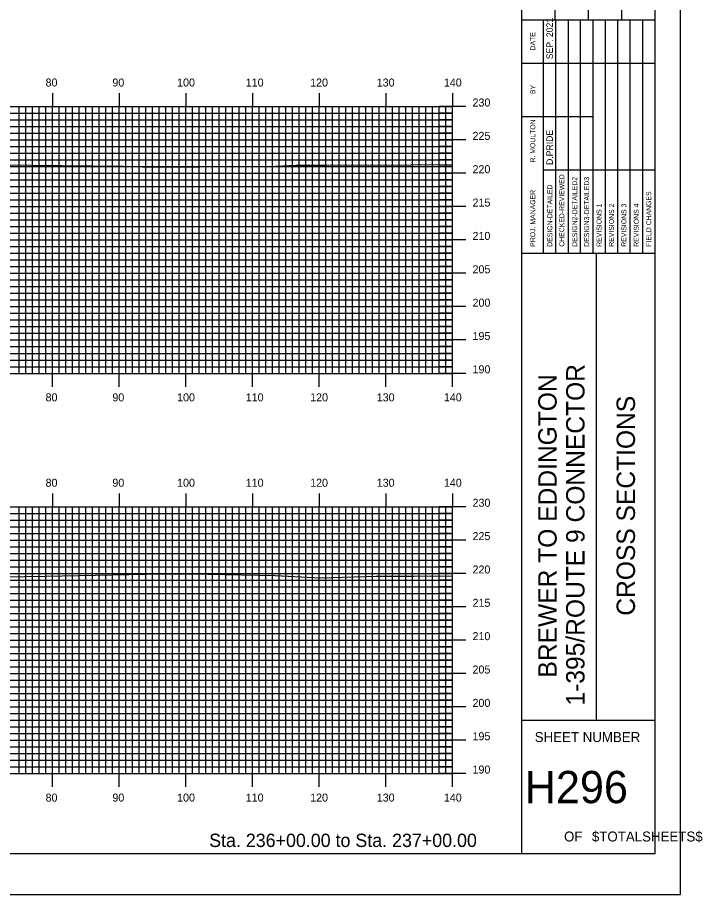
# Model space of a CAD drawing. Extents: x 1800749 to 1801092, y 442591 to 442811.
# Drawn here: x 1800989.3 to 1801092, y 442590.5 to 442722 of the extents above; entities that cross this region are included whole.
import ezdxf

# ---------------------------------------------------------------- set-up
doc = ezdxf.new("R2010")
doc.units = 0
for name, color, linetype in [('ANNOTATION', 7, 'Continuous'), ('BORDER', 7, 'Continuous'), ('H_V ANNOTATION', 7, 'Continuous'), ('MAJOR', 7, 'Continuous'), ('MINOR', 7, 'Continuous'), ('PLOT BOUNDARY', 7, 'Continuous'), ('S_Roadway_Centerline', 7, 'Continuous')]:
    doc.layers.add(name, color=color, linetype=linetype)

msp = doc.modelspace()

# ---------------------------------------------------------------- linework, layer by layer
at = {"layer": 'ANNOTATION'}
msp.add_line((1801054.55, 442688.67), (1801054.55, 442691.67), dxfattribs=at)
at = {"layer": 'BORDER'}
for p, q in [((1801064.95, 442596.67), (1801064.95, 442806.67)), ((1801069.95, 442721.67), (1801069.95, 442738.97)), ((1801074.95, 442721.67), (1801074.95, 442738.97)), ((1801079.95, 442721.67), (1801079.95, 442738.97)), ((1801064.95, 442721.67), (1801084.95, 442721.67)), ((1801064.95, 442686.67), (1801084.95, 442686.67)), ((1801076.13, 442616.67), (1801076.13, 442686.67)), ((1801064.95, 442616.67), (1801084.95, 442616.67))]:
    msp.add_line(p, q, dxfattribs=at)
msp.add_lwpolyline([(1800764.95, 442596.67), (1801084.95, 442596.67), (1801084.95, 442806.67), (1800764.95, 442806.67)], close=True, dxfattribs=at)
for points in [[(1801068.18, 442715.17), (1801068.18, 442721.67)], [(1801070.04, 442686.68), (1801070.04, 442721.67)], [(1801071.91, 442721.67), (1801071.91, 442686.68)], [(1801073.77, 442686.68), (1801073.77, 442721.67)], [(1801075.63, 442686.68), (1801075.63, 442721.67)], [(1801077.5, 442686.68), (1801077.5, 442721.67)], [(1801079.36, 442686.68), (1801079.36, 442721.67)], [(1801081.22, 442686.68), (1801081.22, 442721.67)], [(1801083.09, 442686.68), (1801083.09, 442721.67)], [(1801068.18, 442686.68), (1801068.18, 442720.26)], [(1801064.95, 442715.17), (1801084.95, 442715.17)], [(1801064.95, 442707.17), (1801068.18, 442707.17)], [(1801068.18, 442707.17), (1801075.63, 442707.17)], [(1801068.18, 442699.17), (1801084.95, 442699.17)]]:
    msp.add_lwpolyline(points, dxfattribs=at)
at = {"layer": 'MAJOR'}
for p, q in [((1800994.55, 442710.67), (1800994.55, 442708.67)), ((1801004.55, 442710.67), (1801004.55, 442708.67)), ((1801014.55, 442710.67), (1801014.55, 442708.67)), ((1801024.55, 442710.67), (1801024.55, 442708.67)), ((1801034.55, 442710.67), (1801034.55, 442708.67)), ((1801044.55, 442710.67), (1801044.55, 442708.67)), ((1801054.55, 442710.67), (1801054.55, 442708.67)), ((1800774.55, 442708.67), (1801054.55, 442708.67)), ((1800774.55, 442708.67), (1801054.55, 442708.67)), ((1800994.55, 442668.67), (1800994.55, 442708.67)), ((1801004.55, 442668.67), (1801004.55, 442708.67)), ((1801014.55, 442668.67), (1801014.55, 442708.67)), ((1801024.55, 442668.67), (1801024.55, 442708.67)), ((1801034.55, 442668.67), (1801034.55, 442708.67)), ((1801044.55, 442668.67), (1801044.55, 442708.67)), ((1801056.55, 442708.67), (1801052.55, 442708.67)), ((1801054.55, 442668.67), (1801054.55, 442708.67)), ((1801054.55, 442668.67), (1801054.55, 442708.67)), ((1800774.55, 442703.67), (1801054.55, 442703.67)), ((1801056.55, 442703.67), (1801052.55, 442703.67)), ((1800774.55, 442698.67), (1801054.55, 442698.67)), ((1801056.55, 442698.67), (1801052.55, 442698.67)), ((1800774.55, 442693.67), (1801054.55, 442693.67)), ((1801056.55, 442693.67), (1801052.55, 442693.67)), ((1800774.55, 442688.67), (1801054.55, 442688.67)), ((1801056.55, 442688.67), (1801052.55, 442688.67)), ((1800774.55, 442683.67), (1801054.55, 442683.67)), ((1801056.55, 442683.67), (1801052.55, 442683.67)), ((1800774.55, 442678.67), (1801054.55, 442678.67)), ((1801056.55, 442678.67), (1801052.55, 442678.67)), ((1800774.55, 442673.67), (1801054.55, 442673.67)), ((1801056.55, 442673.67), (1801052.55, 442673.67)), ((1800774.55, 442668.67), (1801054.55, 442668.67)), ((1800774.55, 442668.67), (1801054.55, 442668.67)), ((1800994.55, 442666.66), (1800994.55, 442668.67)), ((1801004.55, 442666.66), (1801004.55, 442668.67)), ((1801014.55, 442666.66), (1801014.55, 442668.67)), ((1801024.55, 442666.66), (1801024.55, 442668.67)), ((1801034.55, 442666.66), (1801034.55, 442668.67)), ((1801044.55, 442666.66), (1801044.55, 442668.67)), ((1801056.55, 442668.67), (1801052.55, 442668.67)), ((1801054.55, 442666.66), (1801054.55, 442668.67)), ((1800994.55, 442650.67), (1800994.55, 442648.67)), ((1801004.55, 442650.67), (1801004.55, 442648.67)), ((1801014.55, 442650.67), (1801014.55, 442648.67)), ((1801024.55, 442650.67), (1801024.55, 442648.67)), ((1801034.55, 442650.67), (1801034.55, 442648.67)), ((1801044.55, 442650.67), (1801044.55, 442648.67)), ((1801054.55, 442650.67), (1801054.55, 442648.67)), ((1800774.55, 442648.67), (1801054.55, 442648.67)), ((1800774.55, 442648.67), (1801054.55, 442648.67)), ((1800994.55, 442608.67), (1800994.55, 442648.67)), ((1801004.55, 442608.67), (1801004.55, 442648.67)), ((1801014.55, 442608.67), (1801014.55, 442648.67)), ((1801024.55, 442608.67), (1801024.55, 442648.67)), ((1801034.55, 442608.67), (1801034.55, 442648.67)), ((1801044.55, 442608.67), (1801044.55, 442648.67)), ((1801056.55, 442648.67), (1801052.55, 442648.67)), ((1801054.55, 442608.67), (1801054.55, 442648.67)), ((1801054.55, 442608.67), (1801054.55, 442648.67)), ((1800774.55, 442643.67), (1801054.55, 442643.67)), ((1801056.55, 442643.67), (1801052.55, 442643.67)), ((1800774.55, 442638.67), (1801054.55, 442638.67)), ((1801056.55, 442638.67), (1801052.55, 442638.67)), ((1800774.55, 442633.67), (1801054.55, 442633.67)), ((1801056.55, 442633.67), (1801052.55, 442633.67)), ((1800774.55, 442628.67), (1801054.55, 442628.67)), ((1801056.55, 442628.67), (1801052.55, 442628.67)), ((1800774.55, 442623.67), (1801054.55, 442623.67)), ((1801056.55, 442623.67), (1801052.55, 442623.67)), ((1800774.55, 442618.67), (1801054.55, 442618.67)), ((1801056.55, 442618.67), (1801052.55, 442618.67)), ((1800774.55, 442613.67), (1801054.55, 442613.67)), ((1801056.55, 442613.67), (1801052.55, 442613.67)), ((1800774.55, 442608.67), (1801054.55, 442608.67)), ((1800774.55, 442608.67), (1801054.55, 442608.67)), ((1800994.55, 442606.66), (1800994.55, 442608.67)), ((1801004.55, 442606.66), (1801004.55, 442608.67)), ((1801014.55, 442606.66), (1801014.55, 442608.67)), ((1801024.55, 442606.66), (1801024.55, 442608.67)), ((1801034.55, 442606.66), (1801034.55, 442608.67)), ((1801044.55, 442606.66), (1801044.55, 442608.67)), ((1801056.55, 442608.67), (1801052.55, 442608.67)), ((1801054.55, 442606.66), (1801054.55, 442608.67))]:
    msp.add_line(p, q, dxfattribs=at)
at = {"layer": 'MINOR'}
for p, q in [((1800989.55, 442668.67), (1800989.55, 442708.67)), ((1800990.55, 442668.67), (1800990.55, 442708.67)), ((1800991.55, 442668.67), (1800991.55, 442708.67)), ((1800992.55, 442668.67), (1800992.55, 442708.67)), ((1800993.55, 442668.67), (1800993.55, 442708.67)), ((1800995.55, 442668.67), (1800995.55, 442708.67)), ((1800996.55, 442668.67), (1800996.55, 442708.67)), ((1800997.55, 442668.67), (1800997.55, 442708.67)), ((1800998.55, 442668.67), (1800998.55, 442708.67)), ((1800999.55, 442668.67), (1800999.55, 442708.67)), ((1801000.55, 442668.67), (1801000.55, 442708.67)), ((1801001.55, 442668.67), (1801001.55, 442708.67)), ((1801002.55, 442668.67), (1801002.55, 442708.67)), ((1801003.55, 442668.67), (1801003.55, 442708.67)), ((1801005.55, 442668.67), (1801005.55, 442708.67)), ((1801006.55, 442668.67), (1801006.55, 442708.67)), ((1801007.55, 442668.67), (1801007.55, 442708.67)), ((1801008.55, 442668.67), (1801008.55, 442708.67)), ((1801009.55, 442668.67), (1801009.55, 442708.67)), ((1801010.55, 442668.67), (1801010.55, 442708.67)), ((1801011.55, 442668.67), (1801011.55, 442708.67)), ((1801012.55, 442668.67), (1801012.55, 442708.67)), ((1801013.55, 442668.67), (1801013.55, 442708.67)), ((1801015.55, 442668.67), (1801015.55, 442708.67)), ((1801016.55, 442668.67), (1801016.55, 442708.67)), ((1801017.55, 442668.67), (1801017.55, 442708.67)), ((1801018.55, 442668.67), (1801018.55, 442708.67)), ((1801019.55, 442668.67), (1801019.55, 442708.67)), ((1801020.55, 442668.67), (1801020.55, 442708.67)), ((1801021.55, 442668.67), (1801021.55, 442708.67)), ((1801022.55, 442668.67), (1801022.55, 442708.67)), ((1801023.55, 442668.67), (1801023.55, 442708.67)), ((1801025.55, 442668.67), (1801025.55, 442708.67)), ((1801026.55, 442668.67), (1801026.55, 442708.67)), ((1801027.55, 442668.67), (1801027.55, 442708.67)), ((1801028.55, 442668.67), (1801028.55, 442708.67)), ((1801029.55, 442668.67), (1801029.55, 442708.67)), ((1801030.55, 442668.67), (1801030.55, 442708.67)), ((1801031.55, 442668.67), (1801031.55, 442708.67)), ((1801032.55, 442668.67), (1801032.55, 442708.67)), ((1801033.55, 442668.67), (1801033.55, 442708.67)), ((1801035.55, 442668.67), (1801035.55, 442708.67)), ((1801036.55, 442668.67), (1801036.55, 442708.67)), ((1801037.55, 442668.67), (1801037.55, 442708.67)), ((1801038.55, 442668.67), (1801038.55, 442708.67)), ((1801039.55, 442668.67), (1801039.55, 442708.67)), ((1801040.55, 442668.67), (1801040.55, 442708.67)), ((1801041.55, 442668.67), (1801041.55, 442708.67)), ((1801042.55, 442668.67), (1801042.55, 442708.67)), ((1801043.55, 442668.67), (1801043.55, 442708.67)), ((1801045.55, 442668.67), (1801045.55, 442708.67)), ((1801046.55, 442668.67), (1801046.55, 442708.67)), ((1801047.55, 442668.67), (1801047.55, 442708.67)), ((1801048.55, 442668.67), (1801048.55, 442708.67)), ((1801049.55, 442668.67), (1801049.55, 442708.67)), ((1801050.55, 442668.67), (1801050.55, 442708.67)), ((1801051.55, 442668.67), (1801051.55, 442708.67)), ((1801052.55, 442668.67), (1801052.55, 442708.67)), ((1801053.55, 442668.67), (1801053.55, 442708.67)), ((1800774.55, 442707.67), (1801054.55, 442707.67)), ((1801054.55, 442707.67), (1801052.55, 442707.67)), ((1800774.55, 442706.67), (1801054.55, 442706.67)), ((1800774.55, 442705.67), (1801054.55, 442705.67)), ((1801054.55, 442706.67), (1801052.55, 442706.67)), ((1801054.55, 442705.67), (1801052.55, 442705.67)), ((1800774.55, 442704.67), (1801054.55, 442704.67)), ((1801054.55, 442704.67), (1801052.55, 442704.67)), ((1800774.55, 442702.67), (1801054.55, 442702.67)), ((1800774.55, 442701.67), (1801054.55, 442701.67)), ((1801054.55, 442702.67), (1801052.55, 442702.67)), ((1801054.55, 442701.67), (1801052.55, 442701.67)), ((1800774.55, 442700.67), (1801054.55, 442700.67)), ((1801054.55, 442700.67), (1801052.55, 442700.67)), ((1800774.55, 442699.67), (1801054.55, 442699.67)), ((1801054.55, 442699.67), (1801052.55, 442699.67)), ((1800774.55, 442697.67), (1801054.55, 442697.67)), ((1801054.55, 442697.67), (1801052.55, 442697.67)), ((1800774.55, 442696.67), (1801054.55, 442696.67)), ((1801054.55, 442696.67), (1801052.55, 442696.67)), ((1800774.55, 442695.67), (1801054.55, 442695.67)), ((1801054.55, 442695.67), (1801052.55, 442695.67)), ((1800774.55, 442694.67), (1801054.55, 442694.67)), ((1801054.55, 442694.67), (1801052.55, 442694.67)), ((1800774.55, 442692.67), (1801054.55, 442692.67)), ((1801054.55, 442692.67), (1801052.55, 442692.67)), ((1800774.55, 442691.67), (1801054.55, 442691.67)), ((1801054.55, 442691.67), (1801052.55, 442691.67)), ((1800774.55, 442690.67), (1801054.55, 442690.67)), ((1801054.55, 442690.67), (1801052.55, 442690.67)), ((1800774.55, 442689.67), (1801054.55, 442689.67)), ((1801054.55, 442689.67), (1801052.55, 442689.67)), ((1800774.55, 442687.67), (1801054.55, 442687.67)), ((1801054.55, 442687.67), (1801052.55, 442687.67)), ((1800774.55, 442686.67), (1801054.55, 442686.67)), ((1801054.55, 442686.67), (1801052.55, 442686.67)), ((1800774.55, 442685.67), (1801054.55, 442685.67)), ((1800774.55, 442684.67), (1801054.55, 442684.67)), ((1801054.55, 442685.67), (1801052.55, 442685.67)), ((1801054.55, 442684.67), (1801052.55, 442684.67)), ((1800774.55, 442682.67), (1801054.55, 442682.67)), ((1801054.55, 442682.67), (1801052.55, 442682.67)), ((1800774.55, 442681.67), (1801054.55, 442681.67)), ((1800774.55, 442680.67), (1801054.55, 442680.67)), ((1801054.55, 442681.67), (1801052.55, 442681.67)), ((1801054.55, 442680.67), (1801052.55, 442680.67)), ((1800774.55, 442679.67), (1801054.55, 442679.67)), ((1801054.55, 442679.67), (1801052.55, 442679.67)), ((1800774.55, 442677.67), (1801054.55, 442677.67)), ((1800774.55, 442676.67), (1801054.55, 442676.67)), ((1801054.55, 442677.67), (1801052.55, 442677.67)), ((1801054.55, 442676.67), (1801052.55, 442676.67)), ((1800774.55, 442675.67), (1801054.55, 442675.67)), ((1801054.55, 442675.67), (1801052.55, 442675.67)), ((1800774.55, 442674.67), (1801054.55, 442674.67)), ((1801054.55, 442674.67), (1801052.55, 442674.67)), ((1800774.55, 442672.67), (1801054.55, 442672.67)), ((1801054.55, 442672.67), (1801052.55, 442672.67)), ((1800774.55, 442671.67), (1801054.55, 442671.67)), ((1801054.55, 442671.67), (1801052.55, 442671.67)), ((1800774.55, 442670.67), (1801054.55, 442670.67)), ((1801054.55, 442670.67), (1801052.55, 442670.67)), ((1800774.55, 442669.67), (1801054.55, 442669.67)), ((1801054.55, 442669.67), (1801052.55, 442669.67)), ((1800774.55, 442647.67), (1801054.55, 442647.67)), ((1800989.55, 442608.67), (1800989.55, 442648.67)), ((1800990.55, 442608.67), (1800990.55, 442648.67)), ((1800991.55, 442608.67), (1800991.55, 442648.67)), ((1800992.55, 442608.67), (1800992.55, 442648.67)), ((1800993.55, 442608.67), (1800993.55, 442648.67)), ((1800995.55, 442608.67), (1800995.55, 442648.67)), ((1800996.55, 442608.67), (1800996.55, 442648.67)), ((1800997.55, 442608.67), (1800997.55, 442648.67)), ((1800998.55, 442608.67), (1800998.55, 442648.67)), ((1800999.55, 442608.67), (1800999.55, 442648.67)), ((1801000.55, 442608.67), (1801000.55, 442648.67)), ((1801001.55, 442608.67), (1801001.55, 442648.67)), ((1801002.55, 442608.67), (1801002.55, 442648.67)), ((1801003.55, 442608.67), (1801003.55, 442648.67)), ((1801005.55, 442608.67), (1801005.55, 442648.67)), ((1801006.55, 442608.67), (1801006.55, 442648.67)), ((1801007.55, 442608.67), (1801007.55, 442648.67)), ((1801008.55, 442608.67), (1801008.55, 442648.67)), ((1801009.55, 442608.67), (1801009.55, 442648.67)), ((1801010.55, 442608.67), (1801010.55, 442648.67)), ((1801011.55, 442608.67), (1801011.55, 442648.67)), ((1801012.55, 442608.67), (1801012.55, 442648.67)), ((1801013.55, 442608.67), (1801013.55, 442648.67)), ((1801015.55, 442608.67), (1801015.55, 442648.67)), ((1801016.55, 442608.67), (1801016.55, 442648.67)), ((1801017.55, 442608.67), (1801017.55, 442648.67)), ((1801018.55, 442608.67), (1801018.55, 442648.67)), ((1801019.55, 442608.67), (1801019.55, 442648.67)), ((1801020.55, 442608.67), (1801020.55, 442648.67)), ((1801021.55, 442608.67), (1801021.55, 442648.67)), ((1801022.55, 442608.67), (1801022.55, 442648.67)), ((1801023.55, 442608.67), (1801023.55, 442648.67)), ((1801025.55, 442608.67), (1801025.55, 442648.67)), ((1801026.55, 442608.67), (1801026.55, 442648.67)), ((1801027.55, 442608.67), (1801027.55, 442648.67)), ((1801028.55, 442608.67), (1801028.55, 442648.67)), ((1801029.55, 442608.67), (1801029.55, 442648.67)), ((1801030.55, 442608.67), (1801030.55, 442648.67)), ((1801031.55, 442608.67), (1801031.55, 442648.67)), ((1801032.55, 442608.67), (1801032.55, 442648.67)), ((1801033.55, 442608.67), (1801033.55, 442648.67)), ((1801035.55, 442608.67), (1801035.55, 442648.67)), ((1801036.55, 442608.67), (1801036.55, 442648.67)), ((1801037.55, 442608.67), (1801037.55, 442648.67)), ((1801038.55, 442608.67), (1801038.55, 442648.67)), ((1801039.55, 442608.67), (1801039.55, 442648.67)), ((1801040.55, 442608.67), (1801040.55, 442648.67)), ((1801041.55, 442608.67), (1801041.55, 442648.67)), ((1801042.55, 442608.67), (1801042.55, 442648.67)), ((1801043.55, 442608.67), (1801043.55, 442648.67)), ((1801045.55, 442608.67), (1801045.55, 442648.67)), ((1801046.55, 442608.67), (1801046.55, 442648.67)), ((1801047.55, 442608.67), (1801047.55, 442648.67)), ((1801048.55, 442608.67), (1801048.55, 442648.67)), ((1801049.55, 442608.67), (1801049.55, 442648.67)), ((1801050.55, 442608.67), (1801050.55, 442648.67)), ((1801051.55, 442608.67), (1801051.55, 442648.67)), ((1801052.55, 442608.67), (1801052.55, 442648.67)), ((1801054.55, 442647.67), (1801052.55, 442647.67)), ((1801053.55, 442608.67), (1801053.55, 442648.67)), ((1800774.55, 442646.67), (1801054.55, 442646.67)), ((1801054.55, 442646.67), (1801052.55, 442646.67)), ((1800774.55, 442645.67), (1801054.55, 442645.67)), ((1801054.55, 442645.67), (1801052.55, 442645.67)), ((1800774.55, 442644.67), (1801054.55, 442644.67)), ((1801054.55, 442644.67), (1801052.55, 442644.67)), ((1800774.55, 442642.67), (1801054.55, 442642.67)), ((1801054.55, 442642.67), (1801052.55, 442642.67)), ((1800774.55, 442641.67), (1801054.55, 442641.67)), ((1801054.55, 442641.67), (1801052.55, 442641.67)), ((1800774.55, 442640.67), (1801054.55, 442640.67)), ((1801054.55, 442640.67), (1801052.55, 442640.67)), ((1800774.55, 442639.67), (1801054.55, 442639.67)), ((1801054.55, 442639.67), (1801052.55, 442639.67)), ((1800774.55, 442637.67), (1801054.55, 442637.67)), ((1801054.55, 442637.67), (1801052.55, 442637.67)), ((1800774.55, 442636.67), (1801054.55, 442636.67)), ((1801054.55, 442636.67), (1801052.55, 442636.67)), ((1800774.55, 442635.67), (1801054.55, 442635.67)), ((1800774.55, 442634.67), (1801054.55, 442634.67)), ((1801054.55, 442635.67), (1801052.55, 442635.67)), ((1801054.55, 442634.67), (1801052.55, 442634.67)), ((1800774.55, 442632.67), (1801054.55, 442632.67)), ((1801054.55, 442632.67), (1801052.55, 442632.67)), ((1800774.55, 442631.67), (1801054.55, 442631.67)), ((1800774.55, 442630.67), (1801054.55, 442630.67)), ((1801054.55, 442631.67), (1801052.55, 442631.67)), ((1801054.55, 442630.67), (1801052.55, 442630.67)), ((1800774.55, 442629.67), (1801054.55, 442629.67)), ((1801054.55, 442629.67), (1801052.55, 442629.67)), ((1800774.55, 442627.67), (1801054.55, 442627.67)), ((1800774.55, 442626.67), (1801054.55, 442626.67)), ((1801054.55, 442627.67), (1801052.55, 442627.67)), ((1801054.55, 442626.67), (1801052.55, 442626.67)), ((1800774.55, 442625.67), (1801054.55, 442625.67)), ((1801054.55, 442625.67), (1801052.55, 442625.67)), ((1800774.55, 442624.67), (1801054.55, 442624.67)), ((1801054.55, 442624.67), (1801052.55, 442624.67)), ((1800774.55, 442622.67), (1801054.55, 442622.67)), ((1801054.55, 442622.67), (1801052.55, 442622.67)), ((1800774.55, 442621.67), (1801054.55, 442621.67)), ((1801054.55, 442621.67), (1801052.55, 442621.67)), ((1800774.55, 442620.67), (1801054.55, 442620.67)), ((1801054.55, 442620.67), (1801052.55, 442620.67)), ((1800774.55, 442619.67), (1801054.55, 442619.67)), ((1801054.55, 442619.67), (1801052.55, 442619.67)), ((1800774.55, 442617.67), (1801054.55, 442617.67)), ((1801054.55, 442617.67), (1801052.55, 442617.67)), ((1800774.55, 442616.67), (1801054.55, 442616.67)), ((1801054.55, 442616.67), (1801052.55, 442616.67)), ((1800774.55, 442615.67), (1801054.55, 442615.67)), ((1801054.55, 442615.67), (1801052.55, 442615.67)), ((1800774.55, 442614.67), (1801054.55, 442614.67)), ((1801054.55, 442614.67), (1801052.55, 442614.67)), ((1800774.55, 442612.67), (1801054.55, 442612.67)), ((1801054.55, 442612.67), (1801052.55, 442612.67)), ((1800774.55, 442611.67), (1801054.55, 442611.67)), ((1801054.55, 442611.67), (1801052.55, 442611.67)), ((1800774.55, 442610.67), (1801054.55, 442610.67)), ((1800774.55, 442609.67), (1801054.55, 442609.67)), ((1801054.55, 442610.67), (1801052.55, 442610.67)), ((1801054.55, 442609.67), (1801052.55, 442609.67))]:
    msp.add_line(p, q, dxfattribs=at)
at = {"layer": 'PLOT BOUNDARY'}
msp.add_lwpolyline([(1800748.76, 442590.55), (1801088.76, 442590.55), (1801088.76, 442810.55), (1800748.76, 442810.55)], close=True, dxfattribs=at)
at = {"layer": 'S_Roadway_Centerline'}
for points in [[(1800986.67, 442699.95), (1801005.14, 442699.75), (1801008.05, 442699.64), (1801011.01, 442699.58), (1801028.01, 442699.75), (1801031.11, 442699.86), (1801035.41, 442699.87), (1801048.29, 442699.94), (1801049.86, 442699.99), (1801054.55, 442699.92)], [(1800984.04, 442638.09), (1800993.51, 442638.26), (1801006, 442638.49), (1801011.31, 442638.6), (1801017.86, 442638.55), (1801027.93, 442638.34), (1801034.73, 442638.03), (1801043.09, 442638.26), (1801048.75, 442638.26), (1801054.55, 442638.32)]]:
    msp.add_lwpolyline(points, dxfattribs=at)

# ---------------------------------------------------------------- texts
at = {"layer": 'BORDER'}
for s, height, p in [('SEP. 2021', 0.969, (1801069.6, 442715.76)), ('DATE', 0.743, (1801066.96, 442717.08)), ('BY', 0.743, (1801066.96, 442710.54)), ('R. MOULTON', 0.745, (1801066.96, 442700.28)), ('D.PRIDE', 0.969, (1801069.6, 442699.92)), ('CHECKED-REVIEWED', 0.7455, (1801071.31, 442687.65)), ('DESIGN2-DETAILED2', 0.7455, (1801073.25, 442687.65)), ('DESIGN3-DETAILED3', 0.7455, (1801075.04, 442687.65)), ('DESIGN-DETAILED', 0.7455, (1801069.52, 442687.65)), ('PROJ. MANAGER', 0.7455, (1801066.96, 442687.65)), ('FIELD CHANGES', 0.7455, (1801084.35, 442687.65)), ('REVISIONS 1', 0.7455, (1801076.9, 442687.65)), ('REVISIONS 2', 0.7455, (1801078.76, 442687.65)), ('REVISIONS 3', 0.7455, (1801080.63, 442687.65)), ('REVISIONS 4', 0.7455, (1801082.49, 442687.65)), ('1-395/ROUTE 9 CONNECTOR', 2.7557, (1801074.35, 442618.87)), ('BREWER TO EDDINGTON', 2.7557, (1801070.17, 442623.07)), ('CROSS SECTIONS', 2.7557, (1801081.92, 442632.34))]:
    msp.add_text(s, height=height, rotation=90, dxfattribs=at).set_placement(p)
for s, height, p in [('SHEET NUMBER', 1.4905, (1801066.88, 442613.4)), ('H296', 4.839, (1801065.39, 442604.23)), ('OF', 1.491, (1801071.28, 442598.49)), ('$TOTALSHEETS$', 1.4905, (1801075.46, 442598.49))]:
    msp.add_text(s, height=height, dxfattribs=at).set_placement(p)
at = {"layer": 'H_V ANNOTATION'}
for s, height, p in [('80', 1.2, (1800993.5, 442711.67)), ('90', 1.2, (1801003.52, 442711.67)), ('100', 1.2, (1801013.23, 442711.67)), ('110', 1.2, (1801023.53, 442711.67)), ('120', 1.2, (1801033.19, 442711.67)), ('130', 1.2, (1801043.18, 442711.67)), ('140', 1.2, (1801053.25, 442711.67)), ('230', 1.2, (1801057.55, 442708.67)), ('225', 1.2, (1801057.55, 442703.67)), ('220', 1.2, (1801057.55, 442698.67)), ('215', 1.2, (1801057.55, 442693.67)), ('210', 1.2, (1801057.55, 442688.67)), ('205', 1.2, (1801057.55, 442683.67)), ('200', 1.2, (1801057.55, 442678.67)), ('195', 1.2, (1801057.55, 442673.67)), ('190', 1.2, (1801057.55, 442668.67)), ('80', 1.2, (1800993.5, 442664.47)), ('90', 1.2, (1801003.52, 442664.47)), ('100', 1.2, (1801013.23, 442664.47)), ('110', 1.2, (1801023.53, 442664.47)), ('120', 1.2, (1801033.19, 442664.47)), ('130', 1.2, (1801043.18, 442664.47)), ('140', 1.2, (1801053.25, 442664.47)), ('80', 1.2, (1800993.5, 442651.67)), ('90', 1.2, (1801003.52, 442651.67)), ('100', 1.2, (1801013.23, 442651.67)), ('110', 1.2, (1801023.53, 442651.67)), ('120', 1.2, (1801033.19, 442651.67)), ('130', 1.2, (1801043.18, 442651.67)), ('140', 1.2, (1801053.25, 442651.67)), ('230', 1.2, (1801057.55, 442648.67)), ('225', 1.2, (1801057.55, 442643.67)), ('220', 1.2, (1801057.55, 442638.67)), ('215', 1.2, (1801057.55, 442633.67)), ('210', 1.2, (1801057.55, 442628.67)), ('205', 1.2, (1801057.55, 442623.67)), ('200', 1.2, (1801057.55, 442618.67)), ('195', 1.2, (1801057.55, 442613.67)), ('190', 1.2, (1801057.55, 442608.67)), ('80', 1.2, (1800993.5, 442604.47)), ('90', 1.2, (1801003.52, 442604.47)), ('100', 1.2, (1801013.23, 442604.47)), ('110', 1.2, (1801023.53, 442604.47)), ('120', 1.2, (1801033.19, 442604.47)), ('130', 1.2, (1801043.18, 442604.47)), ('140', 1.2, (1801053.25, 442604.47)), ('Sta. 236+00.00 to Sta. 237+00.00', 2.0004, (1801018.04, 442597.66))]:
    msp.add_text(s, height=height, dxfattribs=at).set_placement(p)

doc.saveas('drawing.dxf')
